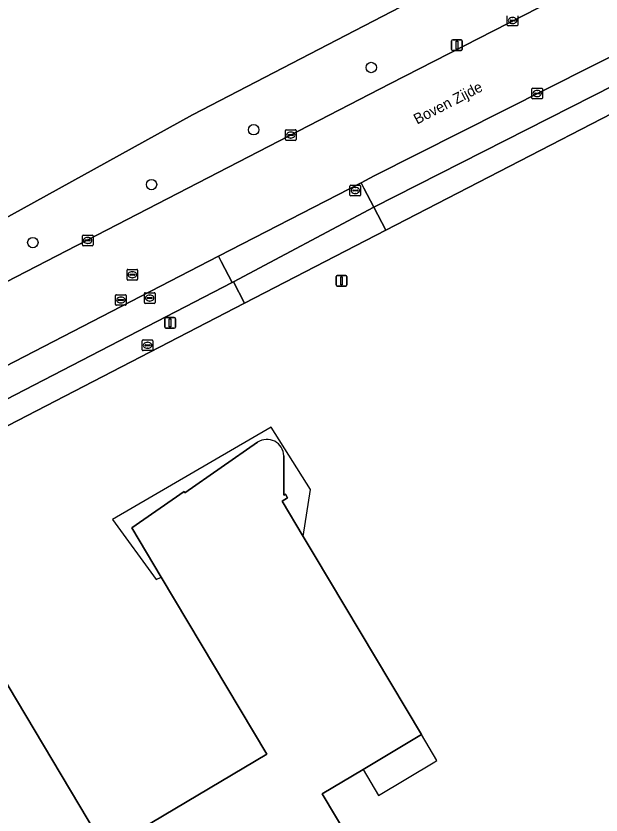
# Model space of a CAD drawing. Extents: x 156702 to 158052, y 387630 to 388992.
# Drawn here: x 157592.9 to 157648, y 388577.4 to 388652.7 of the extents above; entities that cross this region are included whole.
import ezdxf

# ---------------------------------------------------------------- set-up
doc = ezdxf.new("R2010")
doc.units = 0
for name, color, linetype in [('IMGEO_Boom', 7, 'Continuous'), ('IMGEO_Brandkraan', 7, 'Continuous'), ('IMGEO_Erf', 7, 'Continuous'), ('IMGEO_Groenvoorziening', 7, 'Continuous'), ('IMGEO_Kolk', 7, 'Continuous'), ('IMGEO_Lichtmast', 7, 'Continuous'), ('IMGEO_Openbare_ruimte_label', 7, 'Continuous'), ('IMGEO_Pand', 7, 'Continuous'), ('IMGEO_Pand_overbouw', 7, 'Continuous'), ('IMGEO_Parkeervlak_open', 7, 'Continuous'), ('IMGEO_Rijbaan_lokaal_gesloten', 7, 'Continuous'), ('IMGEO_Rioolput', 7, 'Continuous'), ('IMGEO_Voetpad_open', 7, 'Continuous')]:
    doc.layers.add(name, color=color, linetype=linetype)

msp = doc.modelspace()

# ---------------------------------------------------------------- linework, layer by layer
at = {"layer": 'IMGEO_Boom'}
for centre in [(157626.323, 388647.813), (157615.247, 388641.952), (157605.628, 388636.791), (157594.45, 388631.327)]:
    msp.add_circle(centre, 0.489, dxfattribs=at)
at = {"layer": 'IMGEO_Brandkraan'}
for p, q in [((157604.754, 388621.228), (157604.754, 388622.08)), ((157604.829, 388622.154), (157605.681, 388622.154)), ((157605.755, 388622.08), (157605.755, 388621.228)), ((157605.013, 388621.648), (157605.013, 388621.66)), ((157605.451, 388621.611), (157605.053, 388621.611)), ((157605.056, 388621.697), (157605.454, 388621.697)), ((157605.265, 388621.374), (157605.24, 388621.374)), ((157605.242, 388621.934), (157605.267, 388621.934)), ((157605.497, 388621.66), (157605.497, 388621.648)), ((157605.681, 388621.154), (157604.829, 388621.154))]:
    msp.add_line(p, q, dxfattribs=at)
for points in [[(157604.754, 388621.228), (157604.754, 388622.08)], [(157604.829, 388622.154), (157605.681, 388622.154)], [(157605.755, 388622.08), (157605.755, 388621.228)], [(157605.681, 388621.154), (157604.829, 388621.154)]]:
    msp.add_lwpolyline(points, dxfattribs=at)
for centre, radius, start, end in [((157604.831, 388622.078), 0.0765, 91.55205, 178.44795), ((157604.831, 388622.078), 0.0765, 91.55205, 178.44795), ((157605.679, 388622.078), 0.0765, 1.55205, 88.44795), ((157605.679, 388622.078), 0.0765, 1.55205, 88.44795), ((157604.831, 388621.23), 0.0765, 181.55205, 268.44795), ((157604.831, 388621.23), 0.0765, 181.55205, 268.44795), ((157605.053, 388621.657), 0.0403, 85.87752, 175.75265), ((157605.05, 388621.647), 0.0366, 178.93798, 274.71019), ((157605.454, 388621.654), 0.043, 264.86636, 352.45326), ((157605.458, 388621.659), 0.0386, 1.73085, 96.63898), ((157605.679, 388621.23), 0.0765, 271.55205, 358.44795), ((157605.679, 388621.23), 0.0765, 271.55205, 358.44795)]:
    msp.add_arc(centre, radius, start, end, dxfattribs=at)
for centre, major_axis, ratio, start_param, end_param in [((157605.241, 388621.654), (-0.387, 0.002), 0.722429, 4.712389, 7.853982), ((157605.266, 388621.654), (-0.39, 0.002), 0.717154, 1.570796, 4.712389)]:
    msp.add_ellipse(centre, major_axis=major_axis, ratio=ratio, start_param=start_param, end_param=end_param, dxfattribs=at)
at = {"layer": 'IMGEO_Erf'}
for points in [[(157661.638, 388650.018), (157627.71, 388632.506), (157614.38, 388625.618), (157568.072, 388601.671), (157561.726, 388598.389), (157557.204, 388596.047), (157533.162, 388583.611), (157520.661, 388577.166), (157500, 388566.485), (157477.88, 388555.05), (157441.526, 388536.274), (157435.179, 388532.999), (157405.508, 388517.585)], [(157566.652, 388581.958), (157564.089, 388586.251), (157586.207, 388599.432), (157601.327, 388574.137), (157616.479, 388583.151), (157606.543, 388599.828), (157603.779, 388604.468), (157608.702, 388607.878), (157608.776, 388607.772), (157615.62, 388612.53)], [(157618.081, 388611.249), (157618.103, 388607.546), (157618.24, 388607.627), (157618.44, 388607.289), (157617.923, 388606.985), (157619.916, 388603.646), (157620.942, 388601.928), (157631.052, 388584.992), (157625.55, 388581.708), (157621.684, 388579.4), (157643.791, 388542.399), (157626.432, 388532.048), (157627.89, 388529.611), (157605.779, 388516.389), (157566.652, 388581.958)]]:
    msp.add_lwpolyline(points, dxfattribs=at)
msp.add_arc((157616.496, 388611.209), 1.585, 1.45899, 123.54524, dxfattribs=at)
at = {"layer": 'IMGEO_Groenvoorziening'}
for points in [[(157560.912, 388654.14), (157559.756, 388652.604), (157558.427, 388651.534), (157557.951, 388651.125), (157555.68, 388648.696), (157553.403, 388645.635), (157550.686, 388640.549), (157547.892, 388634.814), (157545.72, 388630.048), (157544.055, 388625.147), (157542.079, 388616.922), (157539.19, 388610.071), (157537.398, 388603.555), (157609.481, 388643.37), (157657.977, 388668.537)], [(157657.977, 388668.537), (157609.481, 388643.37), (157537.398, 388603.555)], [(157398.778, 388527.866), (157628.073, 388646.266), (157656.001, 388660.593)]]:
    msp.add_lwpolyline(points, dxfattribs=at)
at = {"layer": 'IMGEO_Kolk'}
for p, q in [((157639.132, 388651.814), (157639.132, 388652.666)), ((157639.391, 388652.234), (157639.391, 388652.246)), ((157639.829, 388652.197), (157639.431, 388652.197)), ((157639.434, 388652.283), (157639.832, 388652.283)), ((157639.62, 388652.52), (157639.645, 388652.52)), ((157639.875, 388652.246), (157639.875, 388652.234)), ((157640.133, 388652.666), (157640.133, 388651.814)), ((157640.059, 388651.74), (157639.207, 388651.74)), ((157639.643, 388651.96), (157639.618, 388651.96)), ((157641.452, 388644.941), (157641.452, 388645.793)), ((157641.527, 388645.867), (157642.379, 388645.867)), ((157641.711, 388645.361), (157641.711, 388645.373)), ((157642.149, 388645.324), (157641.751, 388645.324)), ((157641.754, 388645.41), (157642.152, 388645.41)), ((157641.94, 388645.647), (157641.965, 388645.647)), ((157642.195, 388645.373), (157642.195, 388645.361)), ((157642.453, 388645.793), (157642.453, 388644.941)), ((157642.379, 388644.867), (157641.527, 388644.867)), ((157641.963, 388645.087), (157641.938, 388645.087)), ((157618.244, 388641.025), (157618.244, 388641.877)), ((157618.319, 388641.951), (157619.171, 388641.951)), ((157618.732, 388641.731), (157618.757, 388641.731)), ((157619.245, 388641.877), (157619.245, 388641.025)), ((157619.171, 388640.951), (157618.319, 388640.951)), ((157618.503, 388641.445), (157618.503, 388641.457)), ((157618.941, 388641.408), (157618.543, 388641.408)), ((157618.546, 388641.494), (157618.944, 388641.494)), ((157618.755, 388641.171), (157618.73, 388641.171)), ((157618.987, 388641.457), (157618.987, 388641.445)), ((157624.318, 388635.803), (157624.318, 388636.655)), ((157624.393, 388636.729), (157625.245, 388636.729)), ((157624.62, 388636.272), (157625.018, 388636.272)), ((157624.806, 388636.509), (157624.831, 388636.509)), ((157625.319, 388636.655), (157625.319, 388635.803)), ((157625.245, 388635.729), (157624.393, 388635.729)), ((157624.577, 388636.223), (157624.577, 388636.235)), ((157625.015, 388636.186), (157624.617, 388636.186)), ((157624.829, 388635.949), (157624.804, 388635.949)), ((157625.061, 388636.235), (157625.061, 388636.223)), ((157599.115, 388631.104), (157599.115, 388631.956)), ((157599.19, 388632.03), (157600.042, 388632.03)), ((157599.603, 388631.81), (157599.628, 388631.81)), ((157600.116, 388631.956), (157600.116, 388631.104)), ((157600.042, 388631.03), (157599.19, 388631.03)), ((157599.374, 388631.524), (157599.374, 388631.536)), ((157599.812, 388631.487), (157599.414, 388631.487)), ((157599.417, 388631.573), (157599.815, 388631.573)), ((157599.626, 388631.25), (157599.601, 388631.25)), ((157599.858, 388631.536), (157599.858, 388631.524)), ((157604.957, 388625.676), (157604.957, 388626.528)), ((157605.032, 388626.602), (157605.884, 388626.602)), ((157605.958, 388626.528), (157605.958, 388625.676)), ((157605.216, 388626.096), (157605.216, 388626.108)), ((157605.654, 388626.059), (157605.256, 388626.059)), ((157605.259, 388626.145), (157605.657, 388626.145)), ((157605.468, 388625.822), (157605.443, 388625.822)), ((157605.445, 388626.382), (157605.47, 388626.382)), ((157605.7, 388626.108), (157605.7, 388626.096)), ((157605.884, 388625.602), (157605.032, 388625.602))]:
    msp.add_line(p, q, dxfattribs=at)
for points in [[(157639.132, 388651.814), (157639.132, 388652.666)], [(157640.133, 388652.666), (157640.133, 388651.814)], [(157640.059, 388651.74), (157639.207, 388651.74)], [(157641.452, 388644.941), (157641.452, 388645.793)], [(157641.527, 388645.867), (157642.379, 388645.867)], [(157642.453, 388645.793), (157642.453, 388644.941)], [(157642.379, 388644.867), (157641.527, 388644.867)], [(157618.244, 388641.025), (157618.244, 388641.877)], [(157618.319, 388641.951), (157619.171, 388641.951)], [(157619.245, 388641.877), (157619.245, 388641.025)], [(157619.171, 388640.951), (157618.319, 388640.951)], [(157624.318, 388635.803), (157624.318, 388636.655)], [(157624.393, 388636.729), (157625.245, 388636.729)], [(157625.319, 388636.655), (157625.319, 388635.803)], [(157625.245, 388635.729), (157624.393, 388635.729)], [(157599.115, 388631.104), (157599.115, 388631.956)], [(157599.19, 388632.03), (157600.042, 388632.03)], [(157600.116, 388631.956), (157600.116, 388631.104)], [(157600.042, 388631.03), (157599.19, 388631.03)], [(157604.957, 388625.676), (157604.957, 388626.528)], [(157605.032, 388626.602), (157605.884, 388626.602)], [(157605.958, 388626.528), (157605.958, 388625.676)], [(157605.884, 388625.602), (157605.032, 388625.602)]]:
    msp.add_lwpolyline(points, dxfattribs=at)
for centre, radius, start, end in [((157639.431, 388652.243), 0.0403, 85.87752, 175.75265), ((157639.428, 388652.233), 0.0366, 178.93798, 274.71019), ((157639.832, 388652.24), 0.043, 264.86636, 352.45326), ((157639.836, 388652.245), 0.0386, 1.73085, 96.63898), ((157639.209, 388651.816), 0.0765, 181.55205, 268.44795), ((157639.209, 388651.816), 0.0765, 181.55205, 268.44795), ((157640.057, 388651.816), 0.0765, 271.55205, 358.44795), ((157640.057, 388651.816), 0.0765, 271.55205, 358.44795), ((157641.529, 388645.791), 0.0765, 91.55205, 178.44795), ((157641.529, 388645.791), 0.0765, 91.55205, 178.44795), ((157641.751, 388645.37), 0.0403, 85.87752, 175.75265), ((157641.748, 388645.36), 0.0366, 178.93798, 274.71019), ((157642.152, 388645.367), 0.043, 264.86636, 352.45326), ((157642.156, 388645.372), 0.0386, 1.73085, 96.63898), ((157642.377, 388645.791), 0.0765, 1.55205, 88.44795), ((157642.377, 388645.791), 0.0765, 1.55205, 88.44795), ((157641.529, 388644.943), 0.0765, 181.55205, 268.44795), ((157641.529, 388644.943), 0.0765, 181.55205, 268.44795), ((157642.377, 388644.943), 0.0765, 271.55205, 358.44795), ((157642.377, 388644.943), 0.0765, 271.55205, 358.44795), ((157618.321, 388641.875), 0.0765, 91.55205, 178.44795), ((157618.321, 388641.875), 0.0765, 91.55205, 178.44795), ((157619.169, 388641.875), 0.0765, 1.55205, 88.44795), ((157619.169, 388641.875), 0.0765, 1.55205, 88.44795), ((157618.321, 388641.027), 0.0765, 181.55205, 268.44795), ((157618.321, 388641.027), 0.0765, 181.55205, 268.44795), ((157618.543, 388641.454), 0.0403, 85.87752, 175.75265), ((157618.54, 388641.444), 0.0366, 178.93798, 274.71019), ((157618.944, 388641.451), 0.043, 264.86636, 352.45326), ((157618.948, 388641.456), 0.0386, 1.73085, 96.63898), ((157619.169, 388641.027), 0.0765, 271.55205, 358.44795), ((157619.169, 388641.027), 0.0765, 271.55205, 358.44795), ((157624.395, 388636.653), 0.0765, 91.55205, 178.44795), ((157624.395, 388636.653), 0.0765, 91.55205, 178.44795), ((157624.617, 388636.232), 0.0403, 85.87752, 175.75265), ((157625.022, 388636.234), 0.0386, 1.73085, 96.63898), ((157625.243, 388636.653), 0.0765, 1.55205, 88.44795), ((157625.243, 388636.653), 0.0765, 1.55205, 88.44795), ((157624.395, 388635.805), 0.0765, 181.55205, 268.44795), ((157624.395, 388635.805), 0.0765, 181.55205, 268.44795), ((157624.614, 388636.222), 0.0366, 178.93798, 274.71019), ((157625.018, 388636.229), 0.043, 264.86636, 352.45326), ((157625.243, 388635.805), 0.0765, 271.55205, 358.44795), ((157625.243, 388635.805), 0.0765, 271.55205, 358.44795), ((157599.192, 388631.954), 0.0765, 91.55205, 178.44795), ((157599.192, 388631.954), 0.0765, 91.55205, 178.44795), ((157600.04, 388631.954), 0.0765, 1.55205, 88.44795), ((157600.04, 388631.954), 0.0765, 1.55205, 88.44795), ((157599.192, 388631.106), 0.0765, 181.55205, 268.44795), ((157599.192, 388631.106), 0.0765, 181.55205, 268.44795), ((157599.414, 388631.533), 0.0403, 85.87752, 175.75265), ((157599.411, 388631.523), 0.0366, 178.93798, 274.71019), ((157599.815, 388631.53), 0.043, 264.86636, 352.45326), ((157599.819, 388631.535), 0.0386, 1.73085, 96.63898), ((157600.04, 388631.106), 0.0765, 271.55205, 358.44795), ((157600.04, 388631.106), 0.0765, 271.55205, 358.44795), ((157605.034, 388626.526), 0.0765, 91.55205, 178.44795), ((157605.034, 388626.526), 0.0765, 91.55205, 178.44795), ((157605.882, 388626.526), 0.0765, 1.55205, 88.44795), ((157605.882, 388626.526), 0.0765, 1.55205, 88.44795), ((157605.256, 388626.105), 0.0403, 85.87752, 175.75265), ((157605.253, 388626.095), 0.0366, 178.93798, 274.71019), ((157605.657, 388626.102), 0.043, 264.86636, 352.45326), ((157605.661, 388626.107), 0.0386, 1.73085, 96.63898), ((157605.034, 388625.678), 0.0765, 181.55205, 268.44795), ((157605.034, 388625.678), 0.0765, 181.55205, 268.44795), ((157605.882, 388625.678), 0.0765, 271.55205, 358.44795), ((157605.882, 388625.678), 0.0765, 271.55205, 358.44795)]:
    msp.add_arc(centre, radius, start, end, dxfattribs=at)
for centre, major_axis, ratio, start_param, end_param in [((157639.619, 388652.24), (-0.387, 0.002), 0.722429, 4.712389, 7.853982), ((157639.644, 388652.24), (-0.39, 0.002), 0.717154, 1.570796, 4.712389), ((157641.939, 388645.367), (-0.387, 0.002), 0.722429, 4.712389, 7.853982), ((157641.964, 388645.367), (-0.39, 0.002), 0.717154, 1.570796, 4.712389), ((157618.731, 388641.451), (-0.387, 0.002), 0.722429, 4.712389, 7.853982), ((157618.756, 388641.451), (-0.39, 0.002), 0.717154, 1.570796, 4.712389), ((157624.805, 388636.229), (-0.387, 0.002), 0.722429, 4.712389, 7.853982), ((157624.83, 388636.229), (-0.39, 0.002), 0.717154, 1.570796, 4.712389), ((157599.602, 388631.53), (-0.387, 0.002), 0.722429, 4.712389, 7.853982), ((157599.627, 388631.53), (-0.39, 0.002), 0.717154, 1.570796, 4.712389), ((157605.444, 388626.102), (-0.387, 0.002), 0.722429, 4.712389, 7.853982), ((157605.469, 388626.102), (-0.39, 0.002), 0.717154, 1.570796, 4.712389)]:
    msp.add_ellipse(centre, major_axis=major_axis, ratio=ratio, start_param=start_param, end_param=end_param, dxfattribs=at)
at = {"layer": 'IMGEO_Lichtmast'}
for p, q in [((157633.891, 388649.511), (157633.891, 388650.311)), ((157633.891, 388650.311), (157633.891, 388649.511)), ((157633.991, 388650.411), (157634.781, 388650.411)), ((157634.781, 388650.411), (157633.991, 388650.411)), ((157634.881, 388650.311), (157634.881, 388649.511)), ((157634.881, 388649.511), (157634.881, 388650.311)), ((157634.781, 388649.411), (157633.991, 388649.411)), ((157633.991, 388649.411), (157634.781, 388649.411)), ((157623.027, 388627.333), (157623.027, 388628.133)), ((157623.027, 388628.133), (157623.027, 388627.333)), ((157623.127, 388628.233), (157623.917, 388628.233)), ((157623.917, 388628.233), (157623.127, 388628.233)), ((157624.017, 388628.133), (157624.017, 388627.333)), ((157624.017, 388627.333), (157624.017, 388628.133)), ((157623.917, 388627.233), (157623.127, 388627.233)), ((157623.127, 388627.233), (157623.917, 388627.233)), ((157606.982, 388624.258), (157607.772, 388624.258)), ((157607.772, 388624.258), (157606.982, 388624.258)), ((157606.882, 388623.358), (157606.882, 388624.158)), ((157606.882, 388624.158), (157606.882, 388623.358)), ((157607.872, 388624.158), (157607.872, 388623.358)), ((157607.872, 388623.358), (157607.872, 388624.158)), ((157607.772, 388623.258), (157606.982, 388623.258)), ((157606.982, 388623.258), (157607.772, 388623.258))]:
    msp.add_line(p, q, dxfattribs=at)
for points in [[(157634.311, 388650.286), (157634.461, 388650.286), (157634.461, 388649.536), (157634.311, 388649.536), (157634.311, 388650.286)], [(157623.447, 388628.108), (157623.597, 388628.108), (157623.597, 388627.358), (157623.447, 388627.358), (157623.447, 388628.108)], [(157607.302, 388624.133), (157607.452, 388624.133), (157607.452, 388623.383), (157607.302, 388623.383), (157607.302, 388624.133)]]:
    msp.add_lwpolyline(points, dxfattribs=at)
for centre, start, end in [((157633.991, 388650.311), 90, 180), ((157633.991, 388650.311), 90, 180), ((157634.781, 388650.311), 0, 90), ((157634.781, 388650.311), 360, 90), ((157633.991, 388649.511), 180, 270), ((157633.991, 388649.511), 180, 270), ((157634.781, 388649.511), 270, 0), ((157634.781, 388649.511), 270, 0), ((157623.127, 388628.133), 90, 180), ((157623.127, 388628.133), 90, 180), ((157623.917, 388628.133), 0, 90), ((157623.917, 388628.133), 360, 90), ((157623.127, 388627.333), 180, 270), ((157623.127, 388627.333), 180, 270), ((157623.917, 388627.333), 270, 0), ((157623.917, 388627.333), 270, 0), ((157606.982, 388624.158), 90, 180), ((157606.982, 388624.158), 90, 180), ((157607.772, 388624.158), 0, 90), ((157607.772, 388624.158), 360, 90), ((157606.982, 388623.358), 180, 270), ((157606.982, 388623.358), 180, 270), ((157607.772, 388623.358), 270, 0), ((157607.772, 388623.358), 270, 0)]:
    msp.add_arc(centre, 0.1, start, end, dxfattribs=at)
at = {"layer": 'IMGEO_Pand'}
for points in [[(157615.62, 388612.53), (157608.776, 388607.772), (157608.702, 388607.878), (157603.779, 388604.468), (157606.543, 388599.828), (157616.479, 388583.151), (157601.327, 388574.137), (157586.207, 388599.432), (157564.089, 388586.251), (157566.652, 388581.958), (157605.779, 388516.389), (157627.89, 388529.611), (157626.432, 388532.048), (157643.791, 388542.399), (157621.684, 388579.4)], [(157621.684, 388579.4), (157625.55, 388581.708), (157631.052, 388584.992), (157620.942, 388601.928), (157619.916, 388603.646), (157617.923, 388606.985), (157618.44, 388607.289), (157618.24, 388607.627), (157618.103, 388607.546), (157618.081, 388611.249)]]:
    msp.add_lwpolyline(points, dxfattribs=at)
msp.add_arc((157616.496, 388611.209), 1.585, 1.45899, 123.54524, dxfattribs=at)
at = {"layer": 'IMGEO_Pand_overbouw'}
for points in [[(157618.081, 388611.249), (157618.103, 388607.546), (157618.24, 388607.627), (157618.44, 388607.289), (157617.923, 388606.985), (157619.916, 388603.646), (157620.613, 388608.082), (157616.889, 388613.935), (157601.966, 388605.243), (157606.07, 388599.596), (157606.543, 388599.828)], [(157606.543, 388599.828), (157603.779, 388604.468), (157608.702, 388607.878), (157608.776, 388607.772), (157615.62, 388612.53)]]:
    msp.add_lwpolyline(points, dxfattribs=at)
msp.add_lwpolyline([(157625.55, 388581.708), (157627.006, 388579.269), (157632.316, 388582.439), (157632.508, 388582.553), (157631.052, 388584.992)], close=True, dxfattribs=at)
msp.add_arc((157616.496, 388611.209), 1.585, 1.45899, 123.54524, dxfattribs=at)
at = {"layer": 'IMGEO_Parkeervlak_open'}
msp.add_lwpolyline([(157655.185, 388652.023), (157626.607, 388637.609), (157625.362, 388636.967), (157625.623, 388636.46), (157626.556, 388634.652), (157653.339, 388648.26)], dxfattribs=at)
for points in [[(157626.556, 388634.652), (157625.623, 388636.46), (157625.362, 388636.967), (157611.947, 388630.046), (157612.197, 388629.561), (157613.229, 388627.56), (157613.355, 388627.625)], [(157613.229, 388627.56), (157612.197, 388629.561), (157611.947, 388630.046), (157585.362, 388616.331), (157565.74, 388606.176), (157565.93, 388605.81), (157567.036, 388603.672)]]:
    msp.add_lwpolyline(points, close=True, dxfattribs=at)
at = {"layer": 'IMGEO_Rijbaan_lokaal_gesloten'}
msp.add_lwpolyline([(157656.001, 388660.593), (157628.073, 388646.266), (157398.778, 388527.866), (157402.189, 388521.449), (157403.829, 388522.483), (157404.052, 388522.594), (157412.383, 388526.971), (157431.239, 388536.708), (157432.841, 388537.531), (157439.197, 388540.798), (157445.043, 388543.803), (157456.143, 388549.49), (157474.362, 388558.987), (157509.92, 388577.319), (157518.329, 388581.665), (157530.762, 388588.09), (157551.605, 388598.86), (157554.885, 388600.558), (157565.74, 388606.176), (157585.362, 388616.331), (157611.947, 388630.046), (157625.362, 388636.967), (157626.607, 388637.609), (157655.185, 388652.023)], dxfattribs=at)
at = {"layer": 'IMGEO_Rioolput'}
for p, q in [((157603.393, 388628.799), (157604.245, 388628.799)), ((157603.318, 388627.873), (157603.318, 388628.725)), ((157603.577, 388628.293), (157603.577, 388628.305)), ((157604.015, 388628.256), (157603.617, 388628.256)), ((157603.62, 388628.342), (157604.018, 388628.342)), ((157603.829, 388628.019), (157603.804, 388628.019)), ((157603.806, 388628.579), (157603.831, 388628.579)), ((157604.061, 388628.305), (157604.061, 388628.293)), ((157604.319, 388628.725), (157604.319, 388627.873)), ((157604.245, 388627.799), (157603.393, 388627.799)), ((157602.241, 388625.495), (157602.241, 388626.347)), ((157602.316, 388626.421), (157603.168, 388626.421)), ((157602.5, 388625.915), (157602.5, 388625.927)), ((157602.938, 388625.878), (157602.54, 388625.878)), ((157602.543, 388625.964), (157602.941, 388625.964)), ((157602.729, 388626.201), (157602.754, 388626.201)), ((157602.984, 388625.927), (157602.984, 388625.915)), ((157603.242, 388626.347), (157603.242, 388625.495)), ((157603.168, 388625.421), (157602.316, 388625.421)), ((157602.752, 388625.641), (157602.727, 388625.641))]:
    msp.add_line(p, q, dxfattribs=at)
for points in [[(157603.393, 388628.799), (157604.245, 388628.799)], [(157603.318, 388627.873), (157603.318, 388628.725)], [(157604.319, 388628.725), (157604.319, 388627.873)], [(157604.245, 388627.799), (157603.393, 388627.799)], [(157602.241, 388625.495), (157602.241, 388626.347)], [(157602.316, 388626.421), (157603.168, 388626.421)], [(157603.242, 388626.347), (157603.242, 388625.495)], [(157603.168, 388625.421), (157602.316, 388625.421)]]:
    msp.add_lwpolyline(points, dxfattribs=at)
for centre, radius, start, end in [((157603.395, 388628.723), 0.0765, 91.55205, 178.44795), ((157603.395, 388628.723), 0.0765, 91.55205, 178.44795), ((157604.243, 388628.723), 0.0765, 1.55205, 88.44795), ((157604.243, 388628.723), 0.0765, 1.55205, 88.44795), ((157603.617, 388628.302), 0.0403, 85.87752, 175.75265), ((157603.614, 388628.292), 0.0366, 178.93798, 274.71019), ((157604.018, 388628.299), 0.043, 264.86636, 352.45326), ((157604.022, 388628.304), 0.0386, 1.73085, 96.63898), ((157603.395, 388627.875), 0.0765, 181.55205, 268.44795), ((157603.395, 388627.875), 0.0765, 181.55205, 268.44795), ((157604.243, 388627.875), 0.0765, 271.55205, 358.44795), ((157604.243, 388627.875), 0.0765, 271.55205, 358.44795), ((157602.318, 388626.345), 0.0765, 91.55205, 178.44795), ((157602.318, 388626.345), 0.0765, 91.55205, 178.44795), ((157602.54, 388625.924), 0.0403, 85.87752, 175.75265), ((157602.537, 388625.914), 0.0366, 178.93798, 274.71019), ((157602.941, 388625.921), 0.043, 264.86636, 352.45326), ((157602.945, 388625.926), 0.0386, 1.73085, 96.63898), ((157603.166, 388626.345), 0.0765, 1.55205, 88.44795), ((157603.166, 388626.345), 0.0765, 1.55205, 88.44795), ((157602.318, 388625.497), 0.0765, 181.55205, 268.44795), ((157602.318, 388625.497), 0.0765, 181.55205, 268.44795), ((157603.166, 388625.497), 0.0765, 271.55205, 358.44795), ((157603.166, 388625.497), 0.0765, 271.55205, 358.44795)]:
    msp.add_arc(centre, radius, start, end, dxfattribs=at)
for centre, major_axis, ratio, start_param, end_param in [((157603.805, 388628.299), (-0.387, 0.002), 0.722429, 4.712389, 7.853982), ((157603.83, 388628.299), (-0.39, 0.002), 0.717154, 1.570796, 4.712389), ((157602.728, 388625.921), (-0.387, 0.002), 0.722429, 4.712389, 7.853982), ((157602.753, 388625.921), (-0.39, 0.002), 0.717154, 1.570796, 4.712389)]:
    msp.add_ellipse(centre, major_axis=major_axis, ratio=ratio, start_param=start_param, end_param=end_param, dxfattribs=at)
at = {"layer": 'IMGEO_Voetpad_open'}
msp.add_lwpolyline([(157653.339, 388648.26), (157626.556, 388634.652), (157627.71, 388632.506), (157661.638, 388650.018)], dxfattribs=at)
for points in [[(157627.71, 388632.506), (157626.556, 388634.652), (157613.355, 388627.625), (157614.38, 388625.618)], [(157614.38, 388625.618), (157613.355, 388627.625), (157613.229, 388627.56), (157567.036, 388603.672), (157568.072, 388601.671)]]:
    msp.add_lwpolyline(points, close=True, dxfattribs=at)

# ---------------------------------------------------------------- texts
at = {"layer": 'IMGEO_Openbare_ruimte_label'}
msp.add_text('Boven Zijde', height=1, rotation=27.20592, dxfattribs=at).set_placement((157630.633, 388642.431))

doc.saveas('drawing.dxf')
